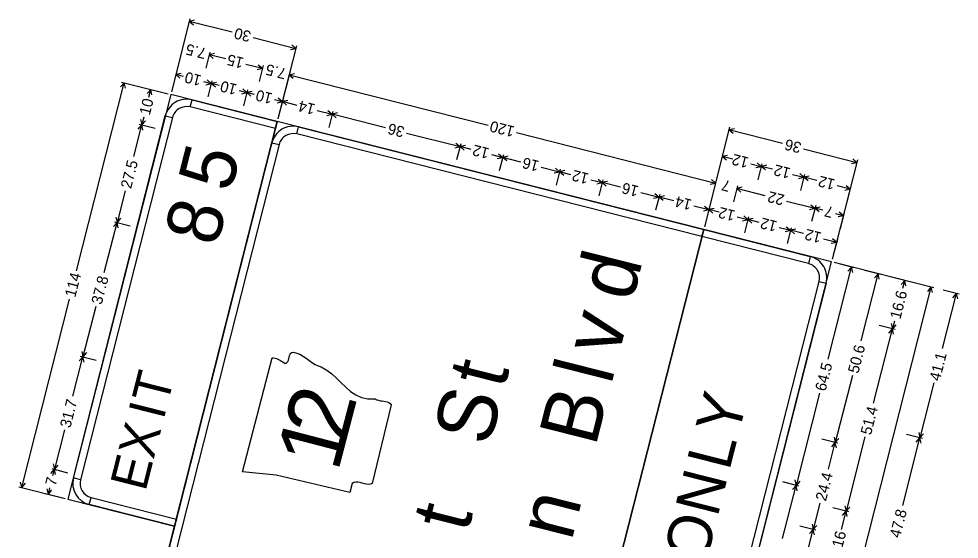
# Model space of a CAD drawing. Extents: x 670009 to 670131, y 737833 to 738002.
# Drawn here: x 670009.28 to 670048.8, y 737881.87 to 737903.76 of the extents above; entities that cross this region are included whole.
import ezdxf

# ---------------------------------------------------------------- set-up
doc = ezdxf.new("R2010")
doc.units = 0
doc.layers.add('R_SIGN', color=7, linetype='Continuous')

msp = doc.modelspace()

# ---------------------------------------------------------------- linework, layer by layer
at = {"layer": 'R_SIGN'}
for p, q in [((670016.474, 737903.763), (670015.695, 737900.692)), ((670016.671, 737903.701), (670016.446, 737903.652)), ((670018.244, 737903.196), (670016.446, 737903.652)), ((670016.62, 737903.501), (670016.446, 737903.652)), ((670019.127, 737902.972), (670020.925, 737902.516)), ((670020.751, 737902.666), (670020.925, 737902.516)), ((670016.191, 737902.647), (670016.021, 737901.976)), ((670017.311, 737902.362), (670017.14, 737901.692)), ((670017.507, 737902.3), (670017.282, 737902.251)), ((670020.954, 737902.627), (670020.175, 737899.556)), ((670020.7, 737902.466), (670020.925, 737902.516)), ((670017.979, 737902.074), (670017.282, 737902.251)), ((670017.457, 737902.1), (670017.282, 737902.251)), ((670015.907, 737901.529), (670015.737, 737900.859)), ((670018.825, 737901.859), (670019.522, 737901.683)), ((670019.297, 737901.633), (670019.522, 737901.683)), ((670019.348, 737901.833), (670019.522, 737901.683)), ((670019.55, 737901.794), (670019.38, 737901.124)), ((670019.55, 737901.794), (670019.38, 737901.124)), ((670020.67, 737901.51), (670020.175, 737899.556)), ((670020.67, 737901.51), (670020.5, 737900.84)), ((670013.6, 737901.104), (670015.555, 737900.608)), ((670016.104, 737901.467), (670015.879, 737901.418)), ((670016.204, 737901.335), (670015.879, 737901.418)), ((670016.053, 737901.267), (670015.879, 737901.418)), ((670017.047, 737901.121), (670017.372, 737901.039)), ((670017.198, 737901.19), (670017.372, 737901.039)), ((670017.4, 737901.151), (670017.231, 737900.481)), ((670017.597, 737901.088), (670017.372, 737901.039)), ((670020.867, 737901.448), (670020.642, 737901.399)), ((670029.001, 737899.279), (670020.642, 737901.399)), ((670020.816, 737901.248), (670020.642, 737901.399)), ((670011.705, 737893.164), (670013.712, 737901.076)), ((670013.561, 737900.901), (670013.712, 737901.076)), ((670013.761, 737900.851), (670013.712, 737901.076)), ((670014.678, 737900.618), (670014.829, 737900.792)), ((670014.717, 737900.821), (670015.387, 737900.651)), ((670014.746, 737900.468), (670014.829, 737900.792)), ((670014.878, 737900.567), (670014.829, 737900.792)), ((670017.147, 737900.99), (670017.372, 737901.039)), ((670017.697, 737900.957), (670017.372, 737901.039)), ((670017.547, 737900.888), (670017.372, 737901.039)), ((670018.54, 737900.743), (670018.865, 737900.66)), ((670018.691, 737900.811), (670018.865, 737900.66)), ((670018.894, 737900.772), (670018.724, 737900.102)), ((670018.894, 737900.772), (670018.724, 737900.102)), ((670019.091, 737900.71), (670018.865, 737900.66)), ((670015.666, 737900.58), (670011.349, 737883.557)), ((670020.146, 737899.444), (670015.666, 737900.58)), ((670016.487, 737900.054), (670016.562, 737900.353)), ((670018.64, 737900.611), (670018.865, 737900.66)), ((670019.19, 737900.578), (670018.865, 737900.66)), ((670019.04, 737900.51), (670018.865, 737900.66)), ((670020.034, 737900.364), (670020.359, 737900.282)), ((670020.184, 737900.432), (670020.359, 737900.282)), ((670020.387, 737900.393), (670020.217, 737899.723)), ((670020.387, 737900.393), (670020.217, 737899.723)), ((670020.584, 737900.331), (670020.359, 737900.282)), ((670020.134, 737900.232), (670020.359, 737900.282)), ((670020.983, 737900.123), (670020.359, 737900.282)), ((670020.533, 737900.131), (670020.359, 737900.282)), ((670021.824, 737899.91), (670022.449, 737899.751)), ((670022.275, 737899.902), (670022.449, 737899.751)), ((670014.401, 737899.524), (670014.45, 737899.299)), ((670014.532, 737899.624), (670014.45, 737899.299)), ((670015.439, 737899.684), (670015.738, 737899.608)), ((670022.224, 737899.702), (670022.449, 737899.751)), ((670022.478, 737899.863), (670022.308, 737899.193)), ((670022.674, 737899.801), (670022.449, 737899.751)), ((670024.692, 737899.182), (670022.449, 737899.751)), ((670022.624, 737899.601), (670022.449, 737899.751)), ((670020.146, 737899.444), (670011.739, 737866.293)), ((670014.112, 737897.966), (670014.45, 737899.299)), ((670014.299, 737899.125), (670014.45, 737899.299)), ((670014.338, 737899.328), (670015.008, 737899.158)), ((670014.338, 737899.328), (670015.008, 737899.158)), ((670014.601, 737899.474), (670014.45, 737899.299)), ((670014.499, 737899.074), (670014.45, 737899.299)), ((670015.829, 737882.421), (670020.146, 737899.444)), ((670038.065, 737894.899), (670020.146, 737899.444)), ((670020.966, 737898.918), (670021.042, 737899.217)), ((670039.156, 737899.2), (670038.094, 737895.011)), ((670039.353, 737899.137), (670039.128, 737899.088)), ((670025.582, 737898.957), (670027.825, 737898.388)), ((670030.202, 737898.974), (670038.561, 737896.854)), ((670041.371, 737898.519), (670039.128, 737899.088)), ((670039.302, 737898.937), (670039.128, 737899.088)), ((670019.919, 737898.548), (670020.218, 737898.472)), ((670027.6, 737898.339), (670027.825, 737898.388)), ((670027.651, 737898.538), (670027.825, 737898.388)), ((670027.853, 737898.5), (670027.683, 737897.829)), ((670028.05, 737898.437), (670027.825, 737898.388)), ((670028.3, 737898.267), (670027.825, 737898.388)), ((670027.999, 737898.237), (670027.825, 737898.388)), ((670029.141, 737898.054), (670029.617, 737897.933)), ((670029.392, 737897.884), (670029.617, 737897.933)), ((670029.442, 737898.084), (670029.617, 737897.933)), ((670029.645, 737898.045), (670029.475, 737897.375)), ((670029.842, 737897.983), (670029.617, 737897.933)), ((670030.386, 737897.738), (670029.617, 737897.933)), ((670029.791, 737897.783), (670029.617, 737897.933)), ((670038.873, 737898.083), (670038.703, 737897.412)), ((670039.07, 737898.02), (670038.844, 737897.971)), ((670039.289, 737897.858), (670038.844, 737897.971)), ((670039.019, 737897.82), (670038.844, 737897.971)), ((670042.261, 737898.293), (670044.503, 737897.724)), ((670040.043, 737897.667), (670040.487, 737897.554)), ((670040.262, 737897.505), (670040.487, 737897.554)), ((670040.313, 737897.705), (670040.487, 737897.554)), ((670040.515, 737897.666), (670040.345, 737896.996)), ((670040.712, 737897.604), (670040.487, 737897.554)), ((670040.963, 737897.434), (670040.487, 737897.554)), ((670040.662, 737897.404), (670040.487, 737897.554)), ((670044.532, 737897.836), (670043.469, 737893.647)), ((670044.278, 737897.675), (670044.503, 737897.724)), ((670044.329, 737897.875), (670044.503, 737897.724)), ((670031.237, 737897.523), (670032.006, 737897.327)), ((670031.781, 737897.278), (670032.006, 737897.327)), ((670031.832, 737897.478), (670032.006, 737897.327)), ((670032.034, 737897.439), (670031.864, 737896.769)), ((670032.231, 737897.377), (670032.006, 737897.327)), ((670032.482, 737897.207), (670032.006, 737897.327)), ((670032.181, 737897.177), (670032.006, 737897.327)), ((670041.803, 737897.22), (670042.279, 737897.1)), ((670042.104, 737897.25), (670042.279, 737897.1)), ((670042.307, 737897.212), (670042.137, 737896.541)), ((670042.307, 737897.212), (670042.137, 737896.541)), ((670042.504, 737897.149), (670042.279, 737897.1)), ((670033.323, 737896.994), (670033.798, 737896.873)), ((670033.573, 737896.824), (670033.798, 737896.873)), ((670033.624, 737897.024), (670033.798, 737896.873)), ((670033.826, 737896.985), (670033.656, 737896.315)), ((670034.023, 737896.922), (670033.798, 737896.873)), ((670034.568, 737896.678), (670033.798, 737896.873)), ((670033.973, 737896.722), (670033.798, 737896.873)), ((670038.589, 737896.966), (670038.094, 737895.011)), ((670038.336, 737896.805), (670038.561, 737896.854)), ((670038.387, 737897.005), (670038.561, 737896.854)), ((670038.589, 737896.966), (670038.419, 737896.295)), ((670039.485, 737896.738), (670039.315, 737896.068)), ((670042.054, 737897.051), (670042.279, 737897.1)), ((670042.827, 737896.961), (670042.279, 737897.1)), ((670042.453, 737896.949), (670042.279, 737897.1)), ((670043.672, 737896.746), (670044.22, 737896.608)), ((670044.046, 737896.758), (670044.22, 737896.608)), ((670013.748, 737896.533), (670013.41, 737895.2)), ((670035.418, 737896.462), (670036.187, 737896.267)), ((670036.013, 737896.418), (670036.187, 737896.267)), ((670036.216, 737896.379), (670036.046, 737895.709)), ((670036.216, 737896.379), (670036.046, 737895.709)), ((670039.682, 737896.676), (670039.457, 737896.627)), ((670040.655, 737896.323), (670039.457, 737896.627)), ((670039.632, 737896.476), (670039.457, 737896.627)), ((670043.995, 737896.558), (670044.22, 737896.608)), ((670044.249, 737896.719), (670044.079, 737896.049)), ((670035.962, 737896.218), (670036.187, 737896.267)), ((670036.412, 737896.316), (670036.187, 737896.267)), ((670036.812, 737896.109), (670036.187, 737896.267)), ((670036.362, 737896.116), (670036.187, 737896.267)), ((670041.545, 737896.097), (670042.742, 737895.794)), ((670037.653, 737895.895), (670038.278, 737895.737)), ((670038.053, 737895.688), (670038.278, 737895.737)), ((670038.103, 737895.887), (670038.278, 737895.737)), ((670038.306, 737895.849), (670038.136, 737895.178)), ((670038.306, 737895.849), (670038.136, 737895.178)), ((670038.503, 737895.786), (670038.278, 737895.737)), ((670038.722, 737895.624), (670038.278, 737895.737)), ((670038.452, 737895.586), (670038.278, 737895.737)), ((670042.517, 737895.744), (670042.742, 737895.794)), ((670042.568, 737895.944), (670042.742, 737895.794)), ((670042.771, 737895.905), (670042.601, 737895.235)), ((670042.771, 737895.905), (670042.601, 737895.235)), ((670042.967, 737895.843), (670042.742, 737895.794)), ((670043.074, 737895.71), (670042.742, 737895.794)), ((670042.917, 737895.643), (670042.742, 737895.794)), ((670043.606, 737895.575), (670043.937, 737895.491)), ((670043.762, 737895.641), (670043.937, 737895.491)), ((670043.965, 737895.602), (670043.795, 737894.932)), ((670012.874, 737893.086), (670013.41, 737895.2)), ((670013.26, 737895.026), (670013.41, 737895.2)), ((670013.299, 737895.229), (670013.969, 737895.059)), ((670013.361, 737895.425), (670013.41, 737895.2)), ((670013.561, 737895.375), (670013.41, 737895.2)), ((670013.46, 737894.975), (670013.41, 737895.2)), ((670039.476, 737895.433), (670039.92, 737895.32)), ((670039.695, 737895.271), (670039.92, 737895.32)), ((670039.746, 737895.471), (670039.92, 737895.32)), ((670039.949, 737895.432), (670039.779, 737894.762)), ((670040.146, 737895.369), (670039.92, 737895.32)), ((670040.396, 737895.2), (670039.92, 737895.32)), ((670040.095, 737895.17), (670039.92, 737895.32)), ((670043.712, 737895.441), (670043.937, 737895.491)), ((670029.658, 737861.749), (670038.065, 737894.899)), ((670038.065, 737894.899), (670029.658, 737861.749)), ((670043.441, 737893.536), (670038.065, 737894.899)), ((670041.237, 737894.986), (670041.712, 737894.866)), ((670041.487, 737894.817), (670041.712, 737894.866)), ((670041.538, 737895.016), (670041.712, 737894.866)), ((670041.741, 737894.977), (670041.571, 737894.307)), ((670041.741, 737894.977), (670041.571, 737894.307)), ((670041.937, 737894.915), (670041.712, 737894.866)), ((670042.26, 737894.727), (670041.712, 737894.866)), ((670041.887, 737894.715), (670041.712, 737894.866)), ((670043.106, 737894.512), (670043.654, 737894.373)), ((670043.428, 737894.324), (670043.654, 737894.373)), ((670043.479, 737894.524), (670043.654, 737894.373)), ((670043.682, 737894.485), (670043.512, 737893.815)), ((670042.545, 737893.763), (670042.469, 737893.464)), ((670035.033, 737860.385), (670043.441, 737893.536)), ((670043.295, 737889.446), (670044.279, 737893.323)), ((670047.742, 737892.445), (670043.553, 737893.507)), ((670044.391, 737893.295), (670043.72, 737893.465)), ((670044.128, 737893.149), (670044.279, 737893.323)), ((670044.328, 737893.098), (670044.279, 737893.323)), ((670045.508, 737893.012), (670044.837, 737893.182)), ((670044.679, 737890.213), (670045.396, 737893.04)), ((670045.245, 737892.865), (670045.396, 737893.04)), ((670045.445, 737892.815), (670045.396, 737893.04)), ((670046.625, 737892.728), (670045.954, 737892.898)), ((670042.915, 737892.716), (670043.214, 737892.64)), ((670043.584, 737876.522), (670047.63, 737892.473)), ((670046.362, 737892.582), (670046.513, 737892.757)), ((670046.431, 737892.432), (670046.513, 737892.757)), ((670046.562, 737892.532), (670046.513, 737892.757)), ((670047.479, 737892.299), (670047.63, 737892.473)), ((670047.679, 737892.248), (670047.63, 737892.473)), ((670048.105, 737889.894), (670048.691, 737892.204)), ((670048.803, 737892.176), (670048.133, 737892.346)), ((670048.54, 737892.03), (670048.691, 737892.204)), ((670048.74, 737891.979), (670048.691, 737892.204)), ((670011.401, 737891.965), (670009.394, 737884.053)), ((670012.513, 737891.663), (670011.977, 737889.548)), ((670046.108, 737890.692), (670045.438, 737890.861)), ((670046.108, 737890.692), (670045.438, 737890.861)), ((670045.947, 737890.945), (670045.996, 737890.72)), ((670046.079, 737891.044), (670045.996, 737890.72)), ((670046.147, 737890.894), (670045.996, 737890.72)), ((670045.204, 737887.596), (670045.996, 737890.72)), ((670045.846, 737890.545), (670045.996, 737890.72)), ((670046.046, 737890.495), (670045.996, 737890.72)), ((670011.928, 737889.773), (670011.977, 737889.548)), ((670012.127, 737889.723), (670011.977, 737889.548)), ((670020.659, 737889.597), (670020.681, 737889.653)), ((670020.681, 737889.653), (670020.713, 737889.699)), ((670020.713, 737889.699), (670020.76, 737889.73)), ((670020.76, 737889.73), (670020.827, 737889.739)), ((670020.827, 737889.739), (670020.967, 737889.705)), ((670020.967, 737889.705), (670021.092, 737889.655)), ((670021.092, 737889.655), (670021.207, 737889.591)), ((670011.557, 737887.892), (670011.977, 737889.548)), ((670011.826, 737889.374), (670011.977, 737889.548)), ((670011.865, 737889.577), (670012.535, 737889.407)), ((670012.026, 737889.323), (670011.977, 737889.548)), ((670018.683, 737884.714), (670019.929, 737889.498)), ((670019.929, 737889.498), (670019.991, 737889.498)), ((670019.929, 737889.498), (670019.929, 737889.498)), ((670019.991, 737889.498), (670020.051, 737889.488)), ((670020.051, 737889.488), (670020.109, 737889.471)), ((670020.109, 737889.471), (670020.165, 737889.449)), ((670020.165, 737889.449), (670020.22, 737889.422)), ((670020.22, 737889.422), (670020.274, 737889.393)), ((670020.274, 737889.393), (670020.328, 737889.361)), ((670020.328, 737889.361), (670020.379, 737889.33)), ((670020.379, 737889.33), (670020.431, 737889.299)), ((670020.431, 737889.299), (670020.483, 737889.27)), ((670020.483, 737889.27), (670020.543, 737889.3)), ((670020.543, 737889.3), (670020.585, 737889.346)), ((670020.585, 737889.346), (670020.612, 737889.403)), ((670020.612, 737889.403), (670020.63, 737889.468)), ((670020.63, 737889.468), (670020.644, 737889.533)), ((670020.644, 737889.533), (670020.659, 737889.597)), ((670021.207, 737889.591), (670021.313, 737889.518)), ((670021.313, 737889.518), (670021.418, 737889.44)), ((670021.418, 737889.44), (670021.521, 737889.362)), ((670021.521, 737889.362), (670021.626, 737889.287)), ((670021.626, 737889.287), (670021.738, 737889.219)), ((670021.738, 737889.219), (670021.858, 737889.162)), ((670021.858, 737889.162), (670021.991, 737889.122)), ((670021.991, 737889.122), (670022.225, 737888.991)), ((670022.225, 737888.991), (670022.437, 737888.827)), ((670022.437, 737888.827), (670022.636, 737888.644)), ((670022.636, 737888.644), (670022.83, 737888.452)), ((670022.83, 737888.452), (670023.024, 737888.263)), ((670044.312, 737888.764), (670043.595, 737885.938)), ((670047.738, 737888.445), (670047.152, 737886.136)), ((670023.024, 737888.263), (670023.227, 737888.089)), ((670023.227, 737888.089), (670023.444, 737887.943)), ((670023.444, 737887.943), (670023.685, 737887.835)), ((670023.685, 737887.835), (670023.954, 737887.778)), ((670023.954, 737887.778), (670024.26, 737887.784)), ((670024.26, 737887.784), (670024.324, 737887.742)), ((670024.324, 737887.742), (670024.395, 737887.716)), ((670024.395, 737887.716), (670024.468, 737887.699)), ((670024.468, 737887.699), (670024.544, 737887.69)), ((670024.544, 737887.69), (670024.62, 737887.682)), ((670024.62, 737887.682), (670024.693, 737887.672)), ((670024.693, 737887.672), (670024.764, 737887.656)), ((670024.764, 737887.656), (670024.828, 737887.629)), ((670042.933, 737888.017), (670041.95, 737884.14)), ((670024.935, 737887.525), (670024.127, 737884.212)), ((670024.828, 737887.629), (670024.886, 737887.587)), ((670024.886, 737887.587), (670024.935, 737887.525)), ((670011.196, 737886.471), (670010.776, 737884.815)), ((670043.706, 737885.91), (670043.036, 737886.08)), ((670043.706, 737885.91), (670043.036, 737886.08)), ((670043.545, 737886.163), (670043.595, 737885.938)), ((670043.745, 737886.112), (670043.595, 737885.938)), ((670044.844, 737886.175), (670044.051, 737883.05)), ((670046.431, 737883.292), (670047.152, 737886.136)), ((670047.264, 737886.107), (670046.593, 737886.277)), ((670047.264, 737886.107), (670046.593, 737886.277)), ((670047.001, 737885.961), (670047.152, 737886.136)), ((670047.103, 737886.361), (670047.152, 737886.136)), ((670047.302, 737886.31), (670047.152, 737886.136)), ((670047.201, 737885.91), (670047.152, 737886.136)), ((670043.312, 737884.824), (670043.595, 737885.938)), ((670043.444, 737885.764), (670043.595, 737885.938)), ((670043.644, 737885.713), (670043.595, 737885.938)), ((670010.727, 737885.04), (670010.776, 737884.815)), ((670010.927, 737884.989), (670010.776, 737884.815)), ((670010.626, 737884.64), (670010.776, 737884.815)), ((670010.665, 737884.843), (670011.335, 737884.673)), ((670010.71, 737884.554), (670010.776, 737884.815)), ((670010.826, 737884.589), (670010.776, 737884.815)), ((670020.095, 737884.562), (670018.683, 737884.714)), ((670023.194, 737883.834), (670020.095, 737884.562)), ((670009.345, 737884.278), (670009.394, 737884.053)), ((670009.545, 737884.227), (670009.394, 737884.053)), ((670011.875, 737884.377), (670011.576, 737884.453)), ((670023.291, 737884.22), (670023.194, 737883.834)), ((670023.368, 737884.26), (670023.291, 737884.22)), ((670023.451, 737884.275), (670023.368, 737884.26)), ((670023.537, 737884.271), (670023.451, 737884.275)), ((670023.627, 737884.255), (670023.537, 737884.271)), ((670023.716, 737884.231), (670023.627, 737884.255)), ((670023.806, 737884.206), (670023.716, 737884.231)), ((670023.893, 737884.185), (670023.806, 737884.206)), ((670023.976, 737884.176), (670023.893, 737884.185)), ((670024.055, 737884.183), (670023.976, 737884.176)), ((670024.127, 737884.212), (670024.055, 737884.183)), ((670041.381, 737881.897), (670041.95, 737884.14)), ((670042.061, 737884.111), (670041.391, 737884.281)), ((670042.061, 737884.111), (670041.391, 737884.281)), ((670041.799, 737883.965), (670041.95, 737884.14)), ((670041.9, 737884.365), (670041.95, 737884.14)), ((670042.1, 737884.314), (670041.95, 737884.14)), ((670041.999, 737883.915), (670041.95, 737884.14)), ((670009.282, 737884.081), (670011.237, 737883.585)), ((670010.4, 737883.798), (670011.07, 737883.628)), ((670010.462, 737883.994), (670010.511, 737883.769)), ((670010.577, 737884.029), (670010.511, 737883.769)), ((670010.662, 737883.944), (670010.511, 737883.769)), ((670011.349, 737883.557), (670015.829, 737882.421)), ((670012.245, 737883.33), (670012.321, 737883.628)), ((670042.95, 737883.396), (670042.668, 737882.282)), ((670044.163, 737883.022), (670043.493, 737883.192)), ((670043.856, 737882.281), (670044.051, 737883.05)), ((670043.901, 737882.876), (670044.051, 737883.05)), ((670044.002, 737883.276), (670044.051, 737883.05)), ((670044.202, 737883.225), (670044.051, 737883.05)), ((670044.1, 737882.825), (670044.051, 737883.05)), ((670015.829, 737882.421), (670015.829, 737882.421)), ((670042.779, 737882.254), (670042.109, 737882.424)), ((670042.472, 737881.513), (670042.668, 737882.282)), ((670042.517, 737882.108), (670042.668, 737882.282)), ((670042.618, 737882.508), (670042.668, 737882.282)), ((670042.818, 737882.457), (670042.668, 737882.282)), ((670042.717, 737882.057), (670042.668, 737882.282))]:
    msp.add_line(p, q, dxfattribs=at)
for points in [[(670020.07, 737899.145), (670016.487, 737900.054), (670016.562, 737900.353), (670020.146, 737899.444), (670020.07, 737899.145)], [(670015.738, 737899.608), (670011.875, 737884.377), (670011.576, 737884.453), (670015.439, 737899.684), (670015.738, 737899.608)], [(670037.99, 737894.6), (670020.966, 737898.918), (670021.042, 737899.217), (670038.065, 737894.899), (670037.99, 737894.6)], [(670020.218, 737898.472), (670012.264, 737867.114), (670011.966, 737867.189), (670019.919, 737898.548), (670020.218, 737898.472)], [(670042.469, 737893.464), (670037.99, 737894.6), (670038.065, 737894.899), (670042.545, 737893.763), (670042.469, 737893.464)], [(670034.962, 737861.357), (670042.915, 737892.716), (670043.214, 737892.64), (670035.261, 737861.281), (670034.962, 737861.357)], [(670012.321, 737883.628), (670015.905, 737882.719), (670015.829, 737882.421), (670012.245, 737883.33), (670012.321, 737883.628)]]:
    msp.add_lwpolyline(points, close=True, dxfattribs=at)
for centre, radius, start, end in [((670016.335, 737899.457), 0.924, 75.7686, 165.7688), ((670016.335, 737899.457), 0.616, 75.7686, 165.7688), ((670020.815, 737898.321), 0.924, 75.7686, 165.7688), ((670020.815, 737898.321), 0.616, 75.7686, 165.7688), ((670042.318, 737892.867), 0.924, 345.7686, 75.7688), ((670042.318, 737892.867), 0.616, 345.7686, 75.7688), ((670012.472, 737884.226), 0.924, 165.7688, 255.7684), ((670012.472, 737884.226), 0.616, 165.7688, 255.7684)]:
    msp.add_arc(centre, radius, start, end, dxfattribs=at)

# ---------------------------------------------------------------- texts
for s, height, rotation, p in [('30', 0.4609, 165.7688, (670019.072, 737903.223)), ('7.5', 0.4609, 165.7688, (670017.2, 737902.509)), ('15', 0.4609, 165.7688, (670018.77, 737902.111)), ('10', 0.4609, 165.7688, (670016.992, 737901.373)), ('7.5', 0.4609, 165.7688, (670020.56, 737901.657)), ('10', 0.4609, 165.7688, (670018.485, 737900.994)), ('10', 0.4609, 165.7688, (670019.979, 737900.616)), ('10', 0.4609, 75.7686, (670014.784, 737899.679)), ('14', 0.4609, 165.7688, (670021.769, 737900.162)), ('36', 0.4609, 165.7688, (670025.527, 737899.208)), ('120', 0.4609, 165.7688, (670030.147, 737899.226)), ('5', 2.311, 75.7686, (670018.187, 737896.42)), ('12', 0.4609, 165.7688, (670029.086, 737898.306)), ('36', 0.4609, 165.7688, (670042.206, 737898.545)), ('16', 0.4609, 165.7688, (670031.182, 737897.774)), ('12', 0.4609, 165.7688, (670039.988, 737897.919)), ('27.5', 0.4609, 75.7686, (670014, 737896.588)), ('12', 0.4609, 165.7688, (670041.748, 737897.472)), ('12', 0.4609, 165.7688, (670033.268, 737897.245)), ('12', 0.4609, 165.7688, (670043.617, 737896.998)), ('16', 0.4609, 165.7688, (670035.363, 737896.714)), ('7', 0.461, 165.7688, (670039.223, 737896.924)), ('22', 0.4609, 165.7688, (670041.49, 737896.349)), ('8', 2.311, 75.7686, (670017.608, 737894.136)), ('14', 0.4609, 165.7688, (670037.598, 737896.147)), ('12', 0.4609, 165.7688, (670039.421, 737895.685)), ('7', 0.461, 165.7688, (670043.551, 737895.826)), ('12', 0.4609, 165.7688, (670041.182, 737895.238)), ('12', 0.4609, 165.7688, (670043.051, 737894.764)), ('d', 2.465, 75.7686, (670035.058, 737891.816)), ('114', 0.4609, 75.7686, (670011.653, 737892.02)), ('37.8', 0.4609, 75.7686, (670012.765, 737891.718)), ('16.6', 0.4609, 75.7686, (670046.33, 737891.099)), ('v', 2.465, 75.7686, (670034.471, 737889.498)), ('50.6', 0.4609, 75.7686, (670044.563, 737888.819)), ('41.1', 0.4609, 75.7686, (670047.989, 737888.5)), ('t', 2.465, 75.7686, (670029.677, 737888.145)), ('l', 2.465, 75.7686, (670034.174, 737888.327)), ('64.5', 0.4609, 75.7686, (670043.185, 737888.072)), ('T', 1.541, 75.7686, (670015.521, 737887.473)), ('2', 2.7, 75.407, (670023.012, 737885.892)), ('S', 2.465, 75.7686, (670029.065, 737885.732)), ('B', 2.465, 75.7686, (670033.513, 737885.723)), ('Y', 1.849, 75.7686, (670039.502, 737886.15)), ('31.7', 0.4609, 75.7686, (670011.448, 737886.526)), ('I', 1.541, 75.7686, (670015.365, 737886.86)), ('51.4', 0.4609, 75.7686, (670045.095, 737886.23)), ('X', 1.541, 75.7686, (670014.943, 737885.194)), ('1', 2.7, 75.407, (670022.692, 737884.664)), ('L', 1.849, 75.7686, (670039.138, 737884.716)), ('E', 1.541, 75.7686, (670014.601, 737883.845)), ('7', 0.461, 75.7686, (670010.829, 737884.084)), ('N', 1.849, 75.7686, (670038.643, 737882.763)), ('24.4', 0.4609, 75.7686, (670043.202, 737883.451)), ('n', 2.465, 75.7686, (670032.507, 737881.757)), ('t', 2.465, 75.7686, (670028.144, 737882.101)), ('47.8', 0.4609, 75.7686, (670046.316, 737881.902)), ('O', 1.849, 75.7686, (670038.152, 737880.828)), ('16', 0.4609, 75.7686, (670043.892, 737881.486))]:
    msp.add_text(s, height=height, rotation=rotation, dxfattribs=at).set_placement(p)

doc.saveas('drawing.dxf')
